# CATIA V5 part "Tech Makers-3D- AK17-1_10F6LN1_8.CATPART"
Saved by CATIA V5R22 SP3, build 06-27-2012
Part number: Tech Makers-3D- AK17-1.10F6LN1.8
Revision: ANY
Definition: UNKNOWN
Nomenclature: Tech Makers-3D- AK17-1.10F6LN1.8
Source: Unknown
Bounding box of the stored display mesh (mm): x -19.5 to 19.501, y -19.501 to 19.7, z 0 to 48
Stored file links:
  \\PSSILO\catalogs\Easy Servo Motores - Leadshine\3D- AK17-1.10F6LN1.8\Cache\9727A645-2A7C-437B-A48D-81238C00F98E.CATPart
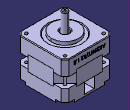
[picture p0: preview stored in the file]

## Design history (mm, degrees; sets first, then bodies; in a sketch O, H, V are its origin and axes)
Body1 "NONE" (main body)
  Solid1: solid without history
Body2 "Extrusão24[7]"
  Solid2: solid without history
Body3 "Padrão circular1"
  Solid3: solid without history
Body4 "Chanfro12"
  Solid4: solid without history
Body5 "Extrusão24[11]"
  Solid5: solid without history
Body6 "Extrusão24[2]"
  Solid6: solid without history
Body7 "Extrusão24[1]"
  Solid7: solid without history
Body8 "Extrusão24[3]"
  Solid8: solid without history
Body9 "Extrusão24[12]"
  Solid9: solid without history
Body10 "Extrusão24[9]"
  Solid10: solid without history
Body11 "Extrusão24[10]"
  Solid11: solid without history
Body12 "Extrusão24[6]"
  Solid12: solid without history
Body13 "Extrusão24[5]"
  Solid13: solid without history
Body14 "Extrusão24[8]"
  Solid14: solid without history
